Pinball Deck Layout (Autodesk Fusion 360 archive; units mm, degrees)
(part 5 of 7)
extrude "Extrude236" add sketch "BackBox" along normal blind 2 bodies "Start (1)"
extrude "Extrude237" new body sketch "BackBox" along normal blind 2 bodies "Coin"
extrude "Extrude238" cut sketch "BackBox" along normal blind 2 bodies "Coin (1)"
extrude "Extrude239" add of existing geometry blind 2
extrude "Extrude240" add sketch "BackBox" along normal blind 2 bodies "Coin (1)"
extrude "Extrude241" new body sketch "BackBox" along normal blind 2 bodies "Player"
extrude "Extrude242" cut sketch "BackBox" along normal blind 2 bodies "Player (1)", "Player (2)", "Player (3)"
extrude "Extrude243" add sketch "BackBox" along normal blind 2 bodies "Player (3)"
extrude "Extrude244" add sketch "BackBox" along normal blind 2 bodies "Player (1)"
extrude "Extrude245" add of existing geometry blind 2 bodies "Player (2)"
sketch "Pinball Machine Case" plane through (0, 0, 0) normal (0, 0, 1) x axis (1, 0, 0)
  line L1 (30, 0) -> (30, 900)
  line L2 (17, -12) -> (17, 0)
  line L3 (513, 0) -> (17, 0)
  line L4 (513, -12) -> (513, 0)
  line L5 (17, -12) -> (513, -12)
  line L6 (513, 1112) -> (513, 0)
  line L7 (501, 1100) -> (501, 0)
  line L8 (29, 1100) -> (29, 0)
  line L9 (17, 1112) -> (17, 0)
  line L10 (17, 1100) -> (513, 1100)
  line L11 (513, 1112) -> (17, 1112)
  line L12 (513, 1100) -> (513, 1112)
  line L13 (17, 1100) -> (17, 1112)
  line L14 (501, 900) -> (29, 900)
  line L15 (501, 912) -> (29, 912)
  point P22 (501, 1100)
  point P23 (29, 1100)
  point P24 (501, 900)
  point P25 (29, 900)
  perpendicular L2 L3
  perpendicular L2 L5
  perpendicular L3 L6
  perpendicular L11 L13
  perpendicular L10 L13
  coincident L10 P22
  coincident L10 P23
  coincident L7 P24
  coincident L8 P25
extrude "Extrude246" new body sketch "Pinball Machine Case" profile of L2 L3 L4 L5 blind 247.006 from offset -147 bodies "Pinball Machine Case Front"
extrude "Extrude247" new body sketch "Pinball Machine Case" profile of L3 L6 L7 L10 blind 400 from offset -147 bodies "Pinball Machine Case Right Side"
extrude "Extrude248" new body sketch "Pinball Machine Case" profile of L3 L8 L9 L10 blind 400 from offset -147 bodies "Pinball Machine Case Left Side"
extrude "Extrude249" new body sketch "Pinball Machine Case" profile of L7 L8 L14 L15 blind 400 from offset -147 bodies "Pinball Machine Case Inner Rear"
extrude "Extrude250" new body sketch "Pinball Machine Case" profile of L6 L9 L10 L11 L12 L13 blind 400 from offset -147 bodies "Pinball Machine Case Outer Rear"
sketch "Pinball Machine Case Internal Left" plane through (29, 0, 0) normal (1, 0, 0) x axis (0, 1, 0)
  line L1 (1100, -147) -> (0, -147)
  line L2 (1100, 253) -> (1100, -147)
  line L3 (0, 253) -> (1100, 253)
  line L4 (0, -147) -> (0, 253)
  line L5 (1227.1774, 0) -> (0, 0)
  line L6 (900, 253) -> (900, -147)
  line L7 (900, 104.1336) -> (0, 0)
  line L8 (900, 84.1336) -> (0, -20)
  line L9 (20, 0) -> (0, 0)
  line L10 (20, -20) -> (0, -20)
  line L11 (20, 0) -> (20, -20)
  line L12 (880, 81.8195) -> (880, 101.8195)
  line L13 (900, 84.1336) -> (900, 104.1336)
  line L14 (900, 101.8195) -> (880, 101.8195)
  line L15 (900, 81.8195) -> (880, 81.8195)
  line L16 (900, 81.8195) -> (900, 84.1336)
  line L17 (900, 253) -> (0, 100.0064)
  point P1 (0, 0)
  point P6 (0, 0)
  point P11 (900, 104.1336)
  point P14 (0, 0)
  point P18 (880, 101.8195)
  point P21 (900, 101.8195)
  horizontal L5
  coincident P1 P6
  coincident L6 P11
  coincident P1 P14
  perpendicular L4 L9
  perpendicular L9 L11
  coincident L7 P18
  perpendicular L13 L14
  coincident L6 P21
  perpendicular L15 L16
extrude "Extrude251" new body sketch "Pinball Machine Case Internal Left" profile of L4 L7 L6 L8 L9 L11 L12 L13 L14 along normal blind 20 bodies "Pinball Machine Left Deck Cleat"
extrude "Extrude252" new body sketch "Pinball Machine Case Internal Left" profile of L4 L7 L6 L8 L9 L11 L12 L13 L14 blind 20 from offset 452 bodies "Pinball Machine Right Deck Cleat"
extrude "Extrude253" new body sketch "Pinball Machine Case Internal Left" profile of L4 L8 L9 L10 L11 blind 430 from offset 21 bodies "Pinball Machine Front Deck Cleat"
extrude "Extrude254" new body sketch "Pinball Machine Case Internal Left" profile of L7 L6 L8 L12 L13 L14 blind 430 from offset 21 bodies "Pinball Machine Rear Deck C;leat"
work_plane "WorkPlane16"
split "Split14" bodies "Pinball Machine Case Right Side (1)"
remove_body "RemoveBody19"
split "Split15" bodies "Pinball Machine Case Left Side (1)"
remove_body "RemoveBody20"
sketch "Bottom of Backboard" plane through (0, 0, 253) normal (0, 0, 1) x axis (-1, 0, 0)
  line L1 (-17, -1112) -> (-513, -1112)
  line L2 (-17, -1100) -> (-17, -1112)
  line L3 (-513, -1100) -> (-17, -1100)
  line L4 (-513, -1112) -> (-513, -1100)
  line L5 (-481, -900) -> (-481, 0)
  line L6 (-480, -20) -> (-50, -20)
  line L7 (-480, -880) -> (-50, -880)
  line L8 (-480, -880) -> (-480, -20)
  line L9 (-50, -880) -> (-480, -880)
  line L10 (-50, -20) -> (-50, -880)
  line L11 (-501, -1100) -> (-501, -912)
  line L12 (-29, -1100) -> (-501, -1100)
  line L13 (-29, -912) -> (-29, -1100)
  line L14 (-501, -912) -> (-29, -912)
  point P6 (-50, -20)
  point P10 (-50, -20)
  point P7 (-480, -20)
  point P11 (-480, -20)
  point P12 (-480, -880)
  point P15 (-480, -880)
  point P16 (-480, -880)
  point P13 (-50, -880)
  point P17 (-50, -880)
  point P18 (-50, -880)
  point P19 (-501, -912)
  point P21 (-501, -912)
  point P20 (-501, -1100)
  point P22 (-501, -1100)
  point P23 (-501, -1100)
  point P25 (-501, -1100)
  point P24 (-29, -1100)
  point P26 (-29, -1100)
  point P27 (-29, -1100)
  point P29 (-29, -1100)
  point P28 (-29, -912)
  point P30 (-29, -912)
  coincident P6 P10
  coincident P7 P11
  coincident P12 P15
  coincident P12 P16
  coincident P13 P17
  coincident P13 P18
  coincident P19 P21
  coincident P20 P22
  coincident P23 P25
  coincident P24 P26
  coincident P27 P29
  coincident P28 P30
extrude "Extrude255" new body sketch "Bottom of Backboard" profile of L3 L11 L12 L13 L14 against normal blind 12 bodies "Rear Support for Backboard"
sketch "Backboard" plane through (0, 0, 253) normal (0, 0, 1) x axis (-1, 0, 0)
  line L1 (-17, -1112) -> (-513, -1112)
  line L2 (-583, -1112) -> (-583, -900)
  line L3 (53, -900) -> (53, -1112)
  line L4 (-583, -1112) -> (53, -1112)
  line L5 (53, -900) -> (-583, -900)
  line L6 (-571, -1112) -> (-571, -900)
  line L7 (41, -900) -> (41, -1112)
  line L8 (-571, -1100) -> (41, -1100)
  line L9 (-571, -912) -> (41, -912)
  line L10 (-571, -924) -> (41, -924)
  point P12 (-571, -1100)
  point P13 (41, -1100)
  perpendicular L2 L4
  perpendicular L3 L5
  coincident L6 P12
  coincident L7 P13
extrude "Extrude256" new body sketch "Backboard" along normal blind 12 bodies "Backboard Base"
extrude "Extrude257" new body sketch "Backboard" profile of L2 L3 L4 L5 L6 L7 blind 400 from offset 12 bodies "Backboard Right Side", "Backboard Left Side"
extrude "Extrude258" new body sketch "Backboard" + "Bottom of Backboard" profile of S2:L1 S2:L2 S2:L3 S2:L4 S2:L11 S2:L12 S2:L13 S2:L14 S1:L1 S1:L2 S1:L3 S1:L4 S1:L5 S1:L6 S1:L7 S1:L8 S1:L9 S1:L10 blind 12 from offset 412 bodies "Backboard Top"
extrude "Extrude259" new body sketch "Backboard" profile of L1 L4 L6 L7 L8 L9 L10 blind 400 from offset 12 bodies "Backboard Rear", "Backboard Front"
sketch "Pinball Case Legs" plane through (0, 0, -147) normal (0, 0, -1) x axis (1, 0, 0)
  line L1 (501, 0) -> (513, 0)
  line L2 (501, -1100) -> (501, 0)
  line L3 (513, -1100) -> (501, -1100)
  line L4 (513, 0) -> (513, -1100)
  line L5 (29, -1100) -> (29, -900)
  line L6 (29, -1055) -> (29, -1100)
  line L7 (74, -1055) -> (29, -1055)
  line L8 (74, -1100) -> (29, -1100)
  line L9 (74, -1055) -> (74, -1100)
  line L10 (74, 0) -> (29, 0)
  line L11 (74, 0) -> (74, -45)
  line L12 (74, -45) -> (29, -45)
  line L13 (29, 0) -> (29, -45)
  line L14 (501, 0) -> (456, 0)
  line L15 (501, 0) -> (501, -45)
  line L16 (501, -45) -> (456, -45)
  line L17 (456, 0) -> (456, -45)
  line L18 (501, -1055) -> (456, -1055)
  line L19 (456, -1055) -> (456, -1100)
  line L20 (501, -1100) -> (456, -1100)
  line L21 (501, -1055) -> (501, -1100)
  point P6 (29, -1100)
  point P9 (29, -1100)
  coincident P6 P9
  parallel L5 L6
  perpendicular L6 L7
  perpendicular L10 L13
  perpendicular L18 L19
  perpendicular L14 L17
extrude "Extrude260" new body sketch "Pinball Case Legs" profile of L2 L5 L6 L7 L8 L9 L10 L11 L12 L13 L14 L15 L16 L17 L18 L19 L20 L21 along normal blind 650 and against normal blind 120 bodies "Leg Left Rear", "Leg Right Rear", "Leg Left Front", "Leg Right Front"
component_from_bodies "Body->Comp1"
component_from_bodies "Body->Comp2"
component_from_bodies "Body->Comp3"
component_from_bodies "Body->Comp4"
component_from_bodies "Body->Comp5"
component_from_bodies "Body->Comp6"
component_from_bodies "Body->Comp7"
component_from_bodies "Body->Comp8"
component_from_bodies "Body->Comp9"
component_from_bodies "Body->Comp10"
component_from_bodies "Body->Comp11"
component_from_bodies "Body->Comp12"
component_from_bodies "Body->Comp13"
component_from_bodies "Body->Comp14"
component_from_bodies "Body->Comp15"
component_from_bodies "Body->Comp16"
component_from_bodies "Body->Comp17"
component_from_bodies "Body->Comp18"
component_from_bodies "Body->Comp19"
component_from_bodies "Body->Comp20"
copy_paste "CutPaste"
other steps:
base_feature "Base Feature1" bodies "Pinball Machine Case Front"
base_feature "Base Feature1" bodies "Leg Right Front"
base_feature "Base Feature1" bodies "Leg Right Rear"
base_feature "Base Feature1" bodies "Leg Left Rear"
base_feature "Base Feature1" bodies "Leg Left Front"
base_feature "Base Feature1" bodies "Pinball Machine Case Right Side"
base_feature "Base Feature1" bodies "Pinball Machine Right Deck Cleat"
base_feature "Base Feature1" bodies "Pinball Machine Case Outer Rear"
base_feature "Base Feature1" bodies "Pinball Machine Left Deck Cleat"
base_feature "Base Feature1" bodies "Pinball Machine Front Deck Cleat"
base_feature "Base Feature1" bodies "Pinball Machine Rear Deck C;leat"
base_feature "Base Feature1" bodies "Pinball Machine Case Left Side"
base_feature "Base Feature1" bodies "Pinball Machine Case Inner Rear"
base_feature "Base Feature1" bodies "Rear Support for Backboard"
base_feature "Base Feature1" bodies "Backboard Base"
base_feature "Base Feature1" bodies "Backboard Right Side"
base_feature "Base Feature1" bodies "Backboard Left Side"
base_feature "Base Feature1" bodies "Backboard Rear"
base_feature "Base Feature1" bodies "Backboard Top"
base_feature "Base Feature1" bodies "Backboard Front"
derived_base_feature "Derived Base Feature" bodies "Flipper_Straight"
base_feature "Base Feature1" bodies "Flipper_Straight (1)"
base_feature "Base Feature2" bodies "Strencil", "Schematic Strencil"
base_feature "Base Feature3" bodies "Transistor", "Transistor Stencil"
base_feature "Base Feature4" bodies "Diode", "Diode Stencil"
base_feature "Base Feature5" bodies "Diode Stencil", "Diode Stencil Fast"
base_feature "Base Feature6" bodies "Transistor Stencil", "Transistor Stencil Fast"
create_component "CreateComponent1"
reparent_decal "ReparentDecal1"
remove_body "RemoveBody21"
create_component "CreateComponent2"
reparent_decal "ReparentDecal2"
remove_body "RemoveBody22"
create_component "CreateComponent3"
reparent_decal "ReparentDecal3"
remove_body "RemoveBody23"
create_component "CreateComponent4"
reparent_decal "ReparentDecal4"
remove_body "RemoveBody24"
create_component "CreateComponent5"
reparent_decal "ReparentDecal5"
remove_body "RemoveBody25"
create_component "CreateComponent6"
reparent_decal "ReparentDecal6"
remove_body "RemoveBody26"
create_component "CreateComponent7"
reparent_decal "ReparentDecal7"
remove_body "RemoveBody27"
create_component "CreateComponent8"
reparent_decal "ReparentDecal8"
remove_body "RemoveBody28"
create_component "CreateComponent9"
reparent_decal "ReparentDecal9"
remove_body "RemoveBody29"
create_component "CreateComponent10"
reparent_decal "ReparentDecal10"
remove_body "RemoveBody30"
create_component "CreateComponent11"
reparent_decal "ReparentDecal11"
remove_body "RemoveBody31"
create_component "CreateComponent12"
reparent_decal "ReparentDecal12"
remove_body "RemoveBody32"
create_component "CreateComponent13"
reparent_decal "ReparentDecal13"
remove_body "RemoveBody33"
create_component "CreateComponent14"
reparent_decal "ReparentDecal14"
remove_body "RemoveBody34"
create_component "CreateComponent15"
reparent_decal "ReparentDecal15"
remove_body "RemoveBody35"
create_component "CreateComponent16"
reparent_decal "ReparentDecal16"
remove_body "RemoveBody36"
create_component "CreateComponent17"
reparent_decal "ReparentDecal17"
remove_body "RemoveBody37"
create_component "CreateComponent18"
reparent_decal "ReparentDecal18"
remove_body "RemoveBody38"
create_component "CreateComponent19"
reparent_decal "ReparentDecal19"
remove_body "RemoveBody39"
create_component "CreateComponent20"
reparent_decal "ReparentDecal20"
remove_body "RemoveBody40"
remove_instance "RemoveInstance1"
named bodies: "Flipper_Straight", "Flipper_Straight (1)", "Left Lower Deck Section", "Middle Lower Deck Section", "Right Lower Deck Section", "Z Reload Plunger", "Reload Ball Release Lower Washer", "Reload Ball Release Drive", "Reload Ball Release Solenoid Coupling", "Reload Ball Release Slide", "Reload Ball Release Slide Coupling", "Left Loweer Deck Section (1)", "Reload Solenoid", "Reload Load Flipper", "Reload Load Coupling", "Reload Load Retaining Washer", "Reload Ball Release Slide (1)", "Reload Ball Release Washer", "Top Right Corner", "Outer Runway Right", "Outer Runway Left", "Right Launch Runway", "Right Launch Runway Top", "Left Middle Runway", "Top Mid Right Overpass", "Top Left Overpass", "Top Mid Left Overpass", "Top Mid Right Overpass Ramp (1)", "Top Mid Right Overpass Ramp (2)", "Top Mid Right Overpass (1)", "Top Mid Right Overpass (2)", "Top Mid Right Overpass Ramp (2) (1)", "Top Mid Right Overpass Ramp (2) (2)", "Top Mid Left Overpass (1)", "Top Mid Left Overpass (2)", "Top Left Corner and ramp down", "Top Left Overpass (1)", "Top Left Overpass (2)", "Left Target Framing", "Left Upper Runway", "Middle Ramp Stand", "Right Mid Launch Runway", "Top Entry Runway", "Ball Reload Positioner", "Strencil", "Schematic Strencil", "Diode", "Transistor", "Transistor Stencil", "Diode Stencil", "Diode Stencil Fast", "Transistor Stencil Fast", "Stripes", "Backbox Electron", "Backbox Electron (1)", "Backbox Electron (2)", "Backbox Bandit", "Backbox Bandit (1)", "Backbox Bandit (2)", "Backbox Bandit (3)"

design "Pinball Flipper Full bushing"
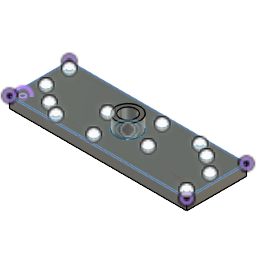
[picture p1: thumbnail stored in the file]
sketch "Flipper" plane through (0, 0, 0) normal (0, 0, 1) x axis (1, 0, 0)
  line L1 (47.7564, -7.9642) -> (0, -12.5)
  line L2 (47.766, 7.9632) -> (1.1968, 12.4426)
  line L3 (-3.0757, 6.1628) -> (6.875, 0.4178)
  line L4 (-6.875, -0.4178) -> (3.0757, -6.1628)
  line L5 (47.7564, 192.0358) -> (0, 187.5)
  line L6 (-6.875, 199.5822) -> (3.0757, 193.8372)
  line L7 (47.766, 207.9632) -> (1.1968, 212.4426)
  line L8 (-3.0757, 206.1628) -> (6.875, 200.4178)
  arc A1 centre (0, 0) radius 12.5 clockwise from (2.3532, -12.2765) to (1.1968, 12.4426)
  arc A2 centre (47, 0) radius 8 clockwise from (47.766, 7.9632) to (47.7564, -7.9642)
  circle C1 centre (0, 0) radius 6.8
  circle C2 centre (3.7239, -2.15) radius 1.4
  circle C3 centre (-3.7239, 2.15) radius 1.4
  arc A3 centre (47, 200) radius 8 clockwise from (47.766, 207.9632) to (47.7564, 192.0358)
  circle C4 centre (-3.7239, 202.15) radius 1.4
  circle C5 centre (0, 200) radius 6.8
  arc A4 centre (0, 200) radius 12.5 clockwise from (2.3532, 187.7235) to (1.1968, 212.4426)
  circle C6 centre (3.7239, 197.85) radius 1.4
  point P1 (0, 0)
  point P2 (0, 0)
  point P4 (0, -12.5)
  point P8 (2.3532, -12.2765)
  point P9 (0, 0)
  point P26 (0, 187.5)
  point P23 (2.3532, 187.7235)
  point P3 (47, 0)
  coincident P1 P2
  coincident P4 A1
  tangent L1 A2
  tangent L2 A1
  tangent L2 A2
  coincident L1 P8
  coincident P1 P9
  coincident P26 A4
  tangent L5 A3
  tangent L7 A4
  tangent A3 L7
  coincident P23 L5
  dimension "d6" diameter C1 = 13.6
  dimension "d174" diameter P3 = 4
  dimension "d363" diameter C2 = 2.8
  dimension "d364" diameter C3 = 2.8
  dimension "d578" diameter C5 = 13.6
  dimension "d579" diameter C6 = 2.8
  dimension "d580" diameter C4 = 2.8
sketch "Bushing" plane through (0, 0, 0) normal (0, 0, 1) x axis (1, 0, 0)
  circle C1 centre (0, 0) radius 7.3
  circle C2 centre (0, 0) radius 11
  circle C3 centre (0, 200) radius 7.3
  circle C4 centre (0, 200) radius 11
  point P1 (0, 0)
  point P2 (0, 0)
  point P3 (0, 0)
  coincident P1 P2
  coincident P1 P3
extrude "Extrude1" new body sketch "Flipper" profile of A1 A2 L1 L2 C1 L4 L3 C2 C3 blind 25 from offset 0.7 bodies "DO NOT USE FLIPPER PROTO"
extrude "Extrude2" add sketch "Flipper" profile of C1 L4 L3 C2 C3 against normal blind 30.8 and along normal blind 0.7
sketch "Washers Upper" plane through (0, 0, 0) normal (0, 0, 1) x axis (1, 0, 0)
  circle C1 centre (0, 0) radius 13.5
  circle C2 centre (0, 0) radius 7.3
  circle C3 centre (0, 200) radius 13.5
  circle C4 centre (0, 200) radius 7.3
  point P1 (0, 0)
  point P2 (0, 0)
  point P3 (0, 0)
  coincident P1 P2
  coincident P1 P3
  dimension "d368" diameter C1 = 27
  dimension "d581" diameter C3 = 27
extrude "Extrude3" new body sketch "Washers Upper" profile of C1 C2 blind -0.8 from offset 0.4 bodies "Washer Upper"
extrude "Extrude4" new body sketch "Bushing" profile of C1 C2 blind -29 from offset -10.2 bodies "Base and Bushing 9mm deck"
sketch "Deck Section" plane through (0, 0, 0) normal (0, 0, 1) x axis (1, 0, 0)
  line L1 (-50, 50) -> (-50, 0)
  line L2 (50, 50) -> (-50, 50)
  line L3 (50, -50) -> (50, 50)
  line L4 (-50, -50) -> (50, -50)
  line L5 (-50, 0) -> (-50, -50)
  circle C1 centre (0, 0) radius 11.5
  point P1 (0, 0)
  point P2 (0, 0)
  coincident P1 P2
  vertical L1
  perpendicular L1 L2
  perpendicular L2 L3
  perpendicular L3 L4
  perpendicular L2 L5
extrude "Extrude5" new body sketch "Deck Section" blind -9 from offset -1.2 bodies "Base Section"
sketch "Solenoid Assembly" plane through (0, 0, -10.2) normal (0, 0, -1) x axis (1, 0, 0)
  line L1 (25, -25) -> (25, 25)
  line L2 (-100, -25) -> (25, -25)
  line L3 (-100, 25) -> (-100, -25)
  line L4 (25, 25) -> (-100, 25)
  line L5 (-100, 225) -> (-100, 175)
  line L6 (25, 175) -> (25, 225)
  line L7 (-100, 175) -> (25, 175)
  line L8 (25, 225) -> (-100, 225)
  circle C1 centre (0, 0) radius 11.5
  circle C2 centre (0, 0) radius 7.3
  circle C3 centre (0, 200) radius 7.3
  point P1 (0, 0)
  point P3 (0, 0)
  coincident P1 P3
  vertical L1
  perpendicular L2 L3
  perpendicular L1 L4
  vertical L6
  perpendicular L5 L7
  perpendicular L6 L8
sketch "Solenoid 22mm" plane through (0, 0, 0) normal (0, 0, 1) x axis (1, 0, 0)
  line L1 (-11, 0) -> (-11, -26)
  line L2 (11, -26) -> (11, 0)
  line L3 (-11, -26) -> (11, -26)
  line L4 (11, 0) -> (-11, 0)
  circle C1 centre (6, -5) radius 1.8
  circle C2 centre (-6, -20) radius 1.8
  point P2 (11, -26)
  point P3 (11, -26)
  point P4 (11, -26)
  coincident P2 P3
  horizontal L3
  perpendicular L1 L3
  perpendicular L1 L4
  coincident P2 P4
  perpendicular L2 L3
sketch "Solenoid 37mm" plane through (0, 0, 0) normal (0, 0, 1) x axis (1, 0, 0)
  line L1 (-2.5, -5.5015) -> (-2.506, -11.3658)
  line L2 (-11, 0) -> (-11, -37)
  line L3 (-5.5, -5.5015) -> (-5.494, -11.3656)
  line L4 (-11, 0) -> (11, 0)
  line L5 (2.5, -31.4995) -> (2.5022, -25.4191)
  line L6 (-2.5, -25.5008) -> (-2.503, -31.4046)
  line L7 (5.5, -25.5) -> (5.5, -31.5)
  line L8 (11, 0) -> (11, -37)
  line L9 (-5.5, -25.5) -> (-5.5, -31.5)
  line L10 (-11, -37) -> (11, -37)
  line L11 (2.5, -5.5015) -> (2.506, -11.3658)
  line L12 (-11, 0) -> (-11, -37)
  line L13 (-11, 0) -> (11, 0)
  line L14 (11, 0) -> (11, -37)
  line L15 (5.5, -5.5015) -> (5.494, -11.3656)
  line L16 (-11, -37) -> (11, -37)
  line L17 (-11, 0) -> (-11, -37)
  line L18 (-11, 0) -> (11, 0)
  line L19 (2.5, -31.4995) -> (2.5021, -25.5799)
  line L20 (5.5, -25.5) -> (5.5, -31.5)
  line L21 (11, 0) -> (11, -37)
  line L22 (-11, -37) -> (11, -37)
  circle C1 centre (4, -28.5) radius 1.5
  arc A1 centre (-4, -31.5) radius 1.5 clockwise from (-2.503, -31.4046) to (-5.5, -31.5)
  arc A2 centre (-4, -25.5) radius 1.5 clockwise from (-5.5, -25.5) to (-2.5, -25.5008)
  arc A3 centre (-4, -11.5) radius 1.5 clockwise from (-2.506, -11.3658) to (-5.494, -11.3656)
  arc A4 centre (4, -11.5) radius 1.5 clockwise from (5.4939, -11.365) to (2.5061, -11.365)
  circle C2 centre (-4, -28.5) radius 1.5
  arc A5 centre (4, -31.5) radius 1.5 clockwise from (5.5, -31.5) to (2.5, -31.4995)
  arc A6 centre (4, -25.5) radius 1.5 clockwise from (2.5022, -25.4191) to (5.5, -25.5)
  arc A7 centre (-4, -5.5) radius 1.5 clockwise from (-5.5, -5.5015) to (-2.5, -5.5015)
  circle C3 centre (-4, -8.5) radius 1.5
  circle C4 centre (4, -8.5) radius 1.5
  circle C5 centre (4, -28.5) radius 1.5
  arc A8 centre (-4, -31.5) radius 1.5 clockwise from (-2.503, -31.4045) to (-5.5, -31.5)
  arc A9 centre (4, -5.5) radius 1.5 clockwise from (2.5, -5.5015) to (5.5, -5.5015)
  arc A10 centre (-4, -11.5) radius 1.5 clockwise from (-2.5061, -11.365) to (-5.4939, -11.365)
  arc A11 centre (4, -11.5) radius 1.5 clockwise from (5.494, -11.3656) to (2.506, -11.3658)
  circle C6 centre (-4, -28.5) radius 1.5
  arc A12 centre (4, -31.5) radius 1.5 clockwise from (5.5, -31.5) to (2.5, -31.4995)
  circle C7 centre (-4, -8.5) radius 1.5
  circle C8 centre (4, -8.5) radius 1.5
  circle C9 centre (4, -28.5) radius 1.5
  arc A13 centre (-4, -31.5) radius 1.5 clockwise from (-2.503, -31.4045) to (-5.5, -31.5)
  arc A14 centre (-4, -11.5) radius 1.5 clockwise from (-2.5061, -11.365) to (-5.4939, -11.365)
  arc A15 centre (4, -11.5) radius 1.5 clockwise from (5.4939, -11.365) to (2.5061, -11.365)
  circle C10 centre (-4, -28.5) radius 1.5
  arc A16 centre (4, -31.5) radius 1.5 clockwise from (5.5, -31.5) to (2.5, -31.4995)
  arc A17 centre (4, -25.5) radius 1.5 clockwise from (2.5021, -25.5799) to (5.5, -25.5)
  circle C11 centre (-4, -8.5) radius 1.5
  circle C12 centre (4, -8.5) radius 1.5
  point P28 (2.5, -31.4995)
  point P7 (2.5, -31.4995)
  point P83 (2.5, -31.4995)
  point P67 (2.5, -31.4995)
  tangent L1 A7
  tangent L3 A7
  tangent A2 L6
  tangent A6 L7
  coincident P28 A5
  tangent A5 L5
  tangent A2 L9
  coincident P7 L5
  tangent A9 L15
  tangent L11 A9
  tangent A17 L20
  coincident P83 A16
  tangent A16 L19
  coincident P67 L19
extrude "Extrude6" new body sketch "Solenoid 22mm" along normal blind 25 bodies "Solenoid 22mm"
extrude "Extrude7" new body sketch "Solenoid 37mm" along normal blind 26 bodies "Solenoid 37mm"
sketch "Solenoid 37mm Plunger" plane through (0, -37, 0) normal (0, -1, 0) x axis (1, 0, 0)
  line L1 (11, 0) -> (-11, 0)
  line L2 (11, 26) -> (11, 0)
  line L3 (-11, 26) -> (11, 26)
  line L4 (-11, 0) -> (-11, 26)
  circle C1 centre (0, 12.5) radius 4
extrude "Extrude8" add sketch "Solenoid 37mm Plunger" profile of C1 along normal blind 23
sketch "Solenoid 22mm Plunger" plane through (0, -26, 0) normal (0, -1, 0) x axis (1, 0, 0)
  line L1 (11, 0) -> (-11, 0)
  line L2 (11, 25) -> (11, 0)
  line L3 (-11, 25) -> (11, 25)
  line L4 (-11, 0) -> (-11, 25)
  circle C1 centre (0, 12.5) radius 4
extrude "Extrude9" add sketch "Solenoid 22mm Plunger" profile of C1 along normal blind 20
sketch "Washer Lower TBA" plane through (0, 0, -10.2) normal (0, 0, -1) x axis (1, 0, 0)
  circle C1 centre (0, 0) radius 15
  circle C2 centre (0, 0) radius 11.5
  circle C3 centre (0, 200) radius 15
  circle C4 centre (0, 200) radius 11.5
  dimension "d38" diameter C1 = 30
  dimension "d582" diameter C3 = 30
move_face "MoveFace1"
extrude "Extrude11" cut sketch "Flipper" profile of C1 L4 L3 blind -19 taper 3 from offset -22.3
sketch "Flipper Drive" plane through (0, 0, -10.2) normal (0, 0, -1) x axis (1, 0, 0)
  line L1 (-0.123, 7.0989) -> (-6.7129, -2.3124)
  line L2 (6.7129, 2.3124) -> (0.123, -7.0989)
  line L3 (-12.2873, 8.6036) -> (0, 0)
  line L4 (-3.5311, 12.3916) -> (-8.1915, 5.7358)
  line L5 (9.4727, 26.0261) -> (0, 0)
  line L6 (25.5365, 11.9079) -> (0, 0)
  line L7 (-11.1615, -30.666) -> (0, 0)
  line L8 (30.0891, 14.0308) -> (0, 0)
  line L9 (-3.473, 19.6962) -> (0, 0)
  line L10 (23.9139, 11.1513) -> (0, 0)
  line L11 (-12.8558, 15.3209) -> (0, 0)
  line L12 (25.7028, 11.9854) -> (0, 0)
  line L13 (0, 0) -> (3.473, -19.6962)
  line L14 (0, 0) -> (12.8558, -15.3209)
  line L15 (25.4979, -9.2805) -> (0, 0)
  line L16 (24.592, 11.4674) -> (0, 0)
  line L17 (0, 0) -> (-25.4979, 9.2805)
  line L18 (23.8505, 4.2055) -> (0, 0)
  line L19 (21.9493, 10.2351) -> (0, 0)
  line L20 (0, 0) -> (-24.5999, 0)
  line L21 (19.205, 16.1149) -> (0, 0)
  line L22 (21.4291, 9.9926) -> (0, 0)
  line L23 (0, 0) -> (-15.3639, -18.31)
  line L24 (-20.1737, -24.0421) -> (0, 0)
  line L25 (28.4442, 13.2638) -> (0, 0)
  line L26 (-28.4796, 0) -> (0, 0)
  line L27 (25.8113, 12.036) -> (0, 0)
  line L28 (30.112, 5.3096) -> (23.8505, 4.2055)
  line L29 (25.0112, 20.9869) -> (19.205, 16.1149)
  line L30 (2.8887, 206.4858) -> (-7.0612, 200.7412)
  line L31 (0, 200) -> (5.1764, 180.6815)
  line L32 (29.5346, 192.0862) -> (23.3932, 193.7318)
  line L33 (28.4796, 200) -> (0, 200)
  line L34 (-23.0757, 176.9243) -> (0, 200)
  line L35 (26.3861, 200) -> (0, 200)
  line L36 (33.1997, 200) -> (0, 200)
  line L37 (31.5373, 208.4504) -> (24.2161, 206.4887)
  line L38 (27.1343, 200) -> (0, 200)
  line L39 (24.2184, 200) -> (0, 200)
  line L40 (-7.5, 212.9904) -> (0, 200)
  line L41 (7.0612, 199.2588) -> (-2.8887, 193.5142)
  line L42 (0, 200) -> (-5.1764, 180.6815)
  line L43 (23.6444, 200) -> (0, 200)
  line L44 (0, 200) -> (-21.6626, 189.8986)
  line L45 (-28.4442, 186.7362) -> (0, 200)
  line L46 (0, 200) -> (-22.295, 210.3963)
  line L47 (19.5843, 219.5843) -> (0, 200)
  line L48 (0, 200) -> (-19.1868, 219.1868)
  line L49 (24.2161, 206.4887) -> (0, 200)
  line L50 (28.1764, 200) -> (0, 200)
  line L51 (-25.8113, 212.036) -> (0, 200)
  line L52 (23.3932, 193.7318) -> (0, 200)
  line L53 (28.3599, 200) -> (0, 200)
  line L54 (-5.1764, 219.3185) -> (0, 200)
  line L55 (2.0367, 212.7229) -> (-5, 208.6603)
  line L56 (5.1764, 219.3185) -> (0, 200)
  line L57 (19.1868, 180.8132) -> (0, 200)
  line L58 (31.3847, 200) -> (0, 200)
  line L59 (14.274, 17.0132) -> (0, 0)
  line L60 (22.8697, 27.2586) -> (14.274, 17.0132)
  line L61 (22.194, 0.0202) -> (0, 0)
  line L62 (30.71, 0.0279) -> (22.194, 0.0202)
  line L63 (-0.123, 7.0989) -> (-6.7129, -2.3124)
  line L64 (6.7129, 2.3124) -> (0.123, -7.0989)
  line L65 (2.8887, 6.4858) -> (-7.0612, 0.7412)
  line L66 (7.0612, -0.7412) -> (-2.8887, -6.4858)
  arc A1 centre (0, 0) radius 7.1 clockwise from (0.123, -7.0989) to (-6.7129, -2.3124)
  arc A2 centre (0, 0) radius 7.1 clockwise from (-0.123, 7.0989) to (6.7129, 2.3124)
  circle C1 centre (0, 0) radius 15
  arc A3 centre (0, 0) radius 7.1 clockwise from (-6.7129, -2.3124) to (-0.123, 7.0989)
  arc A4 centre (0, 0) radius 7.1 clockwise from (6.7129, 2.3124) to (0.123, -7.0989)
  arc A5 centre (0, 0) radius 20 clockwise from (-12.8558, 15.3209) to (-3.473, 19.6962)
  arc A6 centre (0, 0) radius 20 clockwise from (12.8558, -15.3209) to (3.473, -19.6962)
  arc A7 centre (0, 0) radius 16 clockwise from (5.4723, 15.0351) to (12.2567, 10.2846)
  arc A8 centre (0, 0) radius 16 clockwise from (15.7569, 2.7784) to (15.0351, -5.4723)
  arc A9 centre (0, 0) radius 16 clockwise from (-5.4723, -15.0351) to (-10.2846, -12.2567)
  arc A10 centre (0, 0) radius 16 clockwise from (-16, 0) to (-15.0351, 5.4723)
  arc A11 centre (0, 0) radius 16 clockwise from (12.2567, 10.2846) to (15.7569, 2.7784)
  arc A12 centre (0, 0) radius 16 clockwise from (-10.2846, -12.2567) to (-16, 0)
  arc A13 centre (0, 0) radius 21 clockwise from (-13.4985, -16.0869) to (-21, 0)
  arc A14 centre (0, 0) radius 26 clockwise from (8.8925, 24.432) to (24.432, -8.8925)
  arc A15 centre (0, 0) radius 26 clockwise from (-8.8925, -24.432) to (-16.7125, -19.9172)
  arc A16 centre (0, 0) radius 26 clockwise from (-26, 0) to (-24.432, 8.8925)
  arc A17 centre (0, 0) radius 26 clockwise from (24.432, -8.8925) to (-8.8925, -24.432)
  arc A18 centre (0, 0) radius 21 clockwise from (-19.7335, 7.1824) to (7.1824, 19.7335)
  arc A19 centre (0, 0) radius 26 clockwise from (-24.432, 8.8925) to (8.8925, 24.432)
  arc A20 centre (0, 0) radius 21 clockwise from (19.7335, -7.1824) to (-7.1824, -19.7335)
  circle C2 centre (-11.3357, -19.6167) radius 1.75
  circle C3 centre (-11.3357, -19.6167) radius 4
  circle C4 centre (-22.3238, 3.9473) radius 1.75
  circle C5 centre (-22.3238, 3.9473) radius 4
  circle C6 centre (11.2096, 19.5842) radius 1.75
  circle C7 centre (11.2096, 19.5842) radius 4
  circle C8 centre (22.1977, -3.9798) radius 1.75
  circle C9 centre (22.1977, -3.9798) radius 4
  arc A21 centre (0, 0) radius 26 clockwise from (-16.7125, -19.9172) to (-26, 0)
  arc A22 centre (0, 200) radius 20 clockwise from (5.1764, 180.6815) to (-5.1764, 180.6815)
  arc A23 centre (0, 200) radius 26 clockwise from (18.3848, 218.3848) to (18.3848, 181.6152)
  circle C10 centre (18.436, 187.0119) radius 4
  arc A24 centre (0, 200) radius 26 clockwise from (-18.3848, 218.3848) to (18.3848, 218.3848)
  arc A25 centre (0, 200) radius 26 clockwise from (18.3848, 181.6152) to (-18.3848, 181.6152)
  arc A26 centre (0, 200) radius 21 clockwise from (-14.8492, 214.8492) to (14.8492, 214.8492)
  circle C11 centre (0, 200) radius 15
  arc A27 centre (0, 200) radius 16 clockwise from (15.4548, 195.8589) to (11.3137, 188.6863)
  arc A28 centre (0, 200) radius 16 clockwise from (-14.5009, 206.7619) to (-11.3137, 211.3137)
  arc A29 centre (0, 200) radius 16 clockwise from (-11.3137, 188.6863) to (-14.5009, 193.2381)
  arc A30 centre (0, 200) radius 16 clockwise from (15.4548, 204.1411) to (15.4548, 195.8589)
  arc A31 centre (0, 200) radius 21 clockwise from (14.8492, 185.1508) to (-14.8492, 185.1508)
  circle C12 centre (18.436, 213.0119) radius 4
  circle C13 centre (18.436, 213.0119) radius 1.75
  arc A32 centre (0, 200) radius 26 clockwise from (-18.3848, 181.6152) to (-23.564, 189.0119)
  arc A33 centre (0, 200) radius 26 clockwise from (-23.564, 210.9881) to (-18.3848, 218.3848)
  circle C14 centre (-18.564, 187.0119) radius 1.75
  circle C15 centre (-18.564, 187.0119) radius 4
  arc A34 centre (0, 200) radius 7.1 clockwise from (-7.0612, 200.7412) to (2.8887, 206.4858)
  circle C16 centre (-18.564, 213.0119) radius 4
  arc A35 centre (0, 200) radius 7.1 clockwise from (7.0612, 199.2588) to (-2.8887, 193.5142)
  arc A36 centre (0, 200) radius 16 clockwise from (-14.5009, 193.2381) to (-14.5009, 206.7619)
  circle C17 centre (-18.564, 213.0119) radius 1.75
  arc A37 centre (0, 200) radius 7.1 clockwise from (-2.8887, 193.5142) to (-7.0612, 200.7412)
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  point P1 (0, 0)
  point P2 (0, 0)
  point P3 (6.7129, 2.3124)
  point P8 (0, 0)
  point P12 (-12.2873, 8.6036)
  point P7 (0, 0)
  point P15 (0, 0)
  point P14 (0, 0)
  point P18 (0, 0)
  point P11 (0, 0)
  point P21 (0, 0)
  point P23 (0, 0)
  point P26 (0, 0)
  point P27 (0, 0)
  point P30 (0, 0)
  point P33 (0, 0)
  point P38 (0, 0)
  point P43 (0, 0)
  point P49 (12.2567, 10.2846)
  point P50 (5.4723, 15.0351)
  point P48 (0, 0)
  point P53 (15.7569, 2.7784)
  point P36 (0, 0)
  point P51 (0, 0)
  point P55 (-10.2846, -12.2567)
  point P54 (0, 0)
  point P57 (-13.4985, -16.0869)
  point P58 (-21, 0)
  point P61 (-16, 0)
  point P60 (-15.0351, 5.4723)
  point P59 (0, 0)
  point P62 (0, 0)
  point P46 (-15.3639, -18.31)
  point P65 (0, 0)
  point P41 (-24.5999, 0)
  point P68 (0, 0)
  point P13 (0, 0)
  point P71 (0, 0)
  point P75 (8.8925, 24.432)
  point P77 (-16.7125, -19.9172)
  point P76 (0, 0)
  point P81 (-26, 0)
  point P79 (0, 0)
  point P82 (0, 0)
  point P85 (-19.7335, 7.1824)
  point P83 (0, 0)
  point P86 (0, 0)
  point P88 (-7.1824, -19.7335)
  point P73 (0, 0)
  point P87 (0, 0)
  point P42 (0, 0)
  point P98 (0, 0)
  point P129 (7.0612, 199.2588)
  point P128 (0, 200)
  point P135 (0, 200)
  point P117 (-7.5, 212.9904)
  point P133 (0, 200)
  point P137 (0, 200)
  point P112 (0, 200)
  point P140 (0, 200)
  point P118 (0, 200)
  point P155 (0, 200)
  point P171 (0, 200)
  point P177 (0, 200)
  point P178 (0, 200)
  point P182 (0, 200)
  point P174 (0, 200)
  point P125 (0, 200)
  point P163 (0, 200)
  point P161 (15.4548, 204.1411)
  point P162 (11.3137, 211.3137)
  point P166 (0, 200)
  point P151 (15.4548, 195.8589)
  point P153 (0, 200)
  point P183 (0, 200)
  point P194 (-14.5009, 193.2381)
  point P191 (-19.0325, 191.125)
  point P192 (-19.0325, 208.875)
  point P176 (-14.5009, 206.7619)
  point P175 (-11.3137, 211.3137)
  point P193 (0, 200)
  point P165 (-21.6626, 189.8986)
  point P185 (0, 200)
  point P168 (-22.295, 210.3963)
  point P109 (0, 200)
  point P113 (0, 200)
  point P121 (0, 200)
  point P105 (18.3848, 218.3848)
  point P144 (-23.564, 189.0119)
  point P99 (0, 200)
  point P148 (-23.564, 210.9881)
  point P147 (0, 200)
  point P190 (0, 200)
  point P149 (0, 200)
  point P146 (-14.8492, 214.8492)
  point P143 (0, 200)
  point P106 (0, 200)
  point P123 (-14.8492, 185.1508)
  point P111 (0, 200)
  point P124 (0, 200)
  point P110 (0, 200)
  point P157 (0, 200)
  point P196 (0, 0)
  point P197 (20.9994, -0.1635)
  point P198 (13.3537, 16.2074)
  point P199 (0, 0)
  point P200 (14.274, 17.0132)
  point P202 (0, 0)
  point P203 (22.194, 0.0202)
  point P205 (0, 0)
  point P207 (-18.7939, 6.8404)
  point P206 (0, 0)
  point P209 (18.7939, -6.8404)
  point P208 (0, 0)
  coincident P1 P2
  coincident P3 A1
  coincident P2 P8
  concentric A1 C1
  coincident C1 P12
  coincident P7 P15
  coincident P14 P18
  coincident P11 P21
  coincident P2 P23
  coincident P26 P27
  coincident P27 P30
  coincident P7 P33
  coincident P11 P38
  coincident P2 P43
  coincident L21 P49
  coincident L5 P50
  coincident P14 P48
  coincident L18 P53
  coincident P36 P51
  coincident L23 P55
  coincident P1 P54
  coincident L23 P57
  coincident L20 P58
  coincident L20 P61
  coincident L17 P60
  coincident P27 P59
  coincident P1 P62
  coincident P46 L24
  parallel L23 L24
  coincident P7 P65
  coincident P41 L26
  parallel L20 L26
  coincident P51 P68
  parallel L18 L28
  parallel L21 L29
  coincident P13 P71
  coincident L5 P75
  coincident L24 P77
  coincident P13 P76
  coincident L26 P81
  coincident P54 P79
  coincident P54 P82
  coincident L17 P85
  coincident P82 P83
  coincident P59 P86
  coincident L7 P88
  coincident P73 P87
  concentric C2 C3
  concentric C4 C5
  concentric C8 C9
  concentric C6 C7
  coincident P42 P98
  coincident P129 A37
  coincident P128 P135
  concentric C11 A37
  coincident P117 C11
  horizontal L50
  coincident P133 P137
  horizontal L36
  coincident P112 P140
  horizontal L35
  coincident P118 P155
  horizontal L53
  coincident P128 P171
  coincident P177 P178
  coincident P177 P182
  horizontal L38
  coincident P133 P174
  horizontal L39
  coincident P118 P125
  horizontal L43
  coincident P128 P163
  coincident P161 L49
  coincident P162 L47
  coincident P112 P166
  coincident P151 L52
  coincident P153 P183
  coincident P194 L44
  coincident P191 L44
  coincident P192 L46
  coincident P176 L46
  coincident P175 L48
  coincident P177 P193
  horizontal L58
  coincident P165 L45
  parallel L44 L45
  horizontal L33
  coincident P133 P185
  coincident P168 L51
  parallel L46 L51
  coincident P109 P153
  parallel L32 L52
  parallel L37 L49
  coincident P113 P121
  coincident P105 L47
  coincident P144 L45
  coincident P99 P113
  coincident P148 L51
  coincident P147 P190
  coincident P149 P190
  coincident P146 L48
  coincident P143 P149
  coincident P106 P193
  coincident P123 L34
  coincident P111 P124
  concentric C14 C15
  concentric C16 C17
  concentric C12 C13
  coincident P110 P157
  coincident P14 P196
  coincident C9 P197
  coincident C7 P198
  coincident P11 P199
  coincident C7 P200
  tangent C7 L59
  tangent C7 L60
  coincident P76 P202
  coincident C9 P203
  tangent C9 L61
  tangent C9 L62
  coincident P59 P205
  coincident L17 P207
  coincident P54 P206
  coincident L15 P209
  coincident P14 P208
  dimension "d299" angle L7 L8 = 135
  dimension "d300" angle L9 L10 = 75
  dimension "d301" angle L11 L12 = 105
  dimension "d302" radius A5 = 20
  dimension "d303" radius A6 = 20
  dimension "d307" radius A7 = 16
  dimension "d309" radius A8 = 16
  dimension "d311" radius A9 = 16
  dimension "d314" radius A10 = 16
  dimension "d513" radius A14 = 26
  dimension "d514" radius A15 = 26
  dimension "d515" radius A16 = 26
  dimension "d517" radius A18 = 21
  dimension "d518" radius A20 = 21
  dimension "d520" diameter C2 = 3.5
  dimension "d521" diameter C3 = 8
  dimension "d522" diameter C4 = 3.5
  dimension "d523" diameter C5 = 8
  dimension "d524" diameter C8 = 3.5
  dimension "d525" diameter C9 = 8
  dimension "d526" diameter C6 = 3.5
  dimension "d527" diameter C7 = 8
  dimension "d583" angle L34 L36 = 135
  dimension "d584" angle L35 L56 = 75
  dimension "d585" angle L53 L54 = 105
  dimension "d586" radius = 20
  dimension "d587" radius A22 = 20
  dimension "d588" radius = 16
  dimension "d589" radius A27 = 16
  dimension "d590" radius A29 = 16
  dimension "d591" radius A28 = 16
  dimension "d592" radius A23 = 26
  dimension "d593" radius A32 = 26
  dimension "d594" radius A33 = 26
  dimension "d595" radius A26 = 21
  dimension "d596" radius A31 = 21
  dimension "d597" diameter C14 = 3.5
  dimension "d598" diameter C15 = 8
  dimension "d599" diameter C17 = 3.5
  dimension "d600" diameter C16 = 8
  dimension "d601" diameter = 3.5
  dimension "d602" diameter C10 = 8
  dimension "d603" diameter C13 = 3.5
  dimension "d604" diameter C12 = 8
  dimension "d730" radius = 21
work_plane "WorkPlane1" RotateAngle 90
sketch "Flipper Drive Perpendicular Plane" plane through (0, 0, 0) normal (-0.5736, 0.8192, 0) x axis (-0.8192, -0.5736, 0)
  circle C1 centre (10, -32.2) radius 2
  circle C2 centre (10, -32.2) radius 4.5
  circle C3 centre (-10, -32.2) radius 2
  circle C4 centre (-10, -32.2) radius 4.5
  dimension "d51" diameter C1 = 4
  dimension "d52" diameter C2 = 9
  dimension "d53" diameter C3 = 4
  dimension "d54" diameter C4 = 9
extrude "Extrude12" new body sketch "Flipper Drive" profile of A2 C1 A3 A4 blind 8.8 from offset 11.2 bodies "Flipper Drive"
extrude "Extrude13" add sketch "Flipper Drive" profile of L1 L2 L3 A3 A4 blind 8.8 taper 3 from offset 11.2
sketch "Flipper Drive Top Labelling" plane through (0, 0, -30.2) normal (0, 0, -1) x axis (1, 0, 0)
  line L1 (3.3862, 6.2405) -> (-7.0975, 0.1877)
  line L2 (-3.3862, -6.2405) -> (7.0975, -0.1877)
  curve K1
  curve K2
  curve K3
  curve K4
  curve K5
  curve K6
  curve K7
  curve K8
  line L3 (10, 0) -> (0, 0)
  line L4 (0.4316, 7.0869) -> (-6.5119, -2.8294)
  line L5 (-0.4316, -7.0869) -> (6.5119, 2.8294)
  arc A1 centre (0, 0) radius 7.1 clockwise from (-3.3862, -6.2405) to (-7.0975, 0.1877)
  circle C1 centre (-5, 8.6603) radius 5
  circle C2 centre (-5, 8.6603) radius 3
  circle C3 centre (-5, 8.6603) radius 1.75
  arc A2 centre (0, 0) radius 7.1 clockwise from (3.3862, 6.2405) to (7.0975, -0.1877)
  circle C4 centre (0, 0) radius 15
  arc A3 centre (0, 0) radius 7.1 clockwise from (-0.4316, -7.0869) to (-6.5119, -2.8294)
  arc A4 centre (0, 0) radius 7.1 clockwise from (0.4316, 7.0869) to (6.5119, 2.8294)
  circle C5 centre (0, 0) radius 15
  circle C6 centre (5, -8.6603) radius 1.75
  circle C7 centre (5, -8.6603) radius 3
  circle C8 centre (5, -8.6603) radius 5
  point P1 (0, 0)
  point P8 (0, 0)
  horizontal L3
  coincident P1 P8
  concentric C1 C2
  concentric C1 C3
  concentric C7 C8
  concentric C6 C8
  dimension "d75" Text1-Height = 5
  dimension "d77" Text2-Height = 3
extrude "Extrude20" cut sketch "Flipper Drive Top Labelling" against normal blind 0.6
sketch "Flipper Drive Lower Assembly" plane through (0, 0, -10.2) normal (0, 0, -1) x axis (1, 0, 0)
  line L1 (40.6874, -6.549) -> (14.7287, 38.4892)
  line L2 (-113.7703, -35.5739) -> (14.7287, 38.4892)
  line L3 (-87.8117, -80.6121) -> (12.9793, -22.5191)
  line L4 (40.6874, -6.549) -> (12.9793, -22.5191)
  line L5 (-87.8117, -80.6121) -> (-113.7703, -35.5739)
  line L6 (20.7934, 41.9847) -> (14.7287, 38.4892)
  line L7 (46.7521, -3.0534) -> (40.6874, -6.549)
  line L8 (-94.1551, -30.9647) -> (-102.8153, -35.9647)
  line L9 (-83.4756, -35.9647) -> (-102.8153, -35.9647)
  line L10 (-90.691, -28.9647) -> (-94.1551, -30.9647)
  line L11 (19.0606, 40.986) -> (14.7287, 38.4892)
  circle C1 centre (0, 0) radius 11
  circle C2 centre (-82.8153, -70.6057) radius 2.25
  circle C3 centre (-102.8153, -35.9647) radius 2.25
  circle C4 centre (12.3745, 30.5207) radius 2.25
  circle C5 centre (32.3745, -4.1204) radius 2.25
  point P1 (0, 0)
  point P2 (0, 0)
  point P9 (-102.8153, -35.9647)
  point P14 (-102.8153, -35.9647)
  point P15 (-94.1551, -30.9647)
  point P17 (-90.691, -28.9647)
  point P3 (14.7287, 38.4892)
  point P18 (19.0606, 40.986)
  coincident P1 P2
  perpendicular L1 L2
  perpendicular L1 L4
  perpendicular L3 L5
  perpendicular L1 L6
  perpendicular L1 L7
  horizontal L9
  coincident P9 P14
  parallel L8 L10
  perpendicular L1 L11
  dimension "d132" diameter C2 = 4.5
  dimension "d135" diameter C3 = 4.5
  dimension "d138" diameter C4 = 4.5
  dimension "d139" diameter C5 = 4.5
  dimension "d348" angle L8 L9 = 30
  dimension "d349" distance P14 P15 = 10
  dimension "d357" distance P15 P17 = 4
  dimension "d534" distance P3 P18 = 5
extrude "Extrude21" add sketch "Flipper Drive Lower Assembly" profile of C1 L1 L2 L3 L4 L5 along normal blind 10
sketch "Washer Lower" plane through (0, 0, -20.2) normal (0, 0, -1) x axis (1, 0, 0)
  circle C1 centre (0, 0) radius 7.3
  circle C2 centre (0, 0) radius 7.3
  circle C3 centre (0, 0) radius 13.5
  circle C4 centre (0, 200) radius 13.5
  circle C5 centre (0, 200) radius 7.3
  point P1 (0, 0)
  point P3 (0, 0)
  coincident P1 P3
  dimension "d369" diameter C3 = 27
  dimension "d605" diameter C4 = 27
extrude "Extrude22" new body sketch "Washer Lower" profile of C1 C2 C3 blind 1 from offset 0.2 bodies "Washer Lower"
move "Move1"
move "Move2"
move "Move3"
move "Move4"
work_plane "WorkPlane2" RotateAngle 0
sketch "Construction to Solenoid" plane through (0, 0, -32.2) normal (0, 0, 1) x axis (1, 0, 0)
  line L1 (-83.0796, 37.5009) -> (-8.1915, -5.7358)
  line L2 (85.6995, -5.7358) -> (-8.1915, -5.7358)
  point P2 (-8.1915, -5.7358)
  point P3 (-8.1915, -5.7358)
  horizontal L2
  coincident P2 P3
  dimension "d87" angle L1 L2 = 150
move "Move5"
work_axis "WorkAxis2"
move "Move6"
move "Move7"
work_plane "WorkPlane3" AlongDistance 12.5
work_plane "WorkPlane4" RotateAngle 0
work_plane "WorkPlane5" RotateAngle 0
